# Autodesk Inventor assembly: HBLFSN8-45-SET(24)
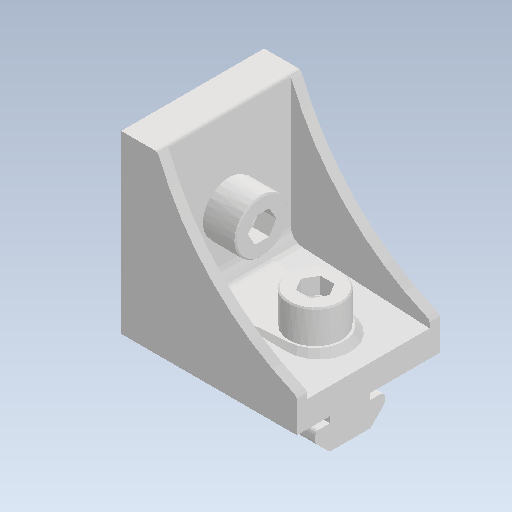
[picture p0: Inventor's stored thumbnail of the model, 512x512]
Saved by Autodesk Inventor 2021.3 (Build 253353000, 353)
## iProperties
Created: 2022-02
Part Number: HBLFSN8-45-SET(24)
Document SubType Name: Assembly
Designer: kengo
Author: kengo
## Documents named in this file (4)
- C:\Users\kengo\Documents\S2S_frame\SDC345\frame_misumi_ver12\HBLFSN8-45-SET(24).iam
- C:\Users\kengo\Documents\S2S_frame\SDC345\frame_misumi_ver12\HBLFSN8-45.ipt
- C:\Users\kengo\Documents\S2S_frame\SDC345\frame_misumi_ver12\HNTT8-8.ipt
- C:\Users\kengo\Documents\S2S_frame\SDC345\frame_misumi_ver12\CBM8-20.ipt
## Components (5 placed, 3 different names)
1. HBLFSN8-45
2. HNTT8-8
3. CBM8-20
4. HNTT8-8:1
5. CBM8-20:1
